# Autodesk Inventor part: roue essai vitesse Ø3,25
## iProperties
Created: 2011-11
Part Number: roue essai vitesse Ø3,25
Document SubType Name: Modeling
Designer: Laur
Density: 1 g/cm^3
Author: Laur
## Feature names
1. Extrusion1
2. Extrusion2
3. Extrusion3
